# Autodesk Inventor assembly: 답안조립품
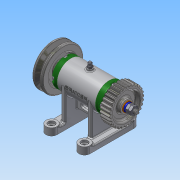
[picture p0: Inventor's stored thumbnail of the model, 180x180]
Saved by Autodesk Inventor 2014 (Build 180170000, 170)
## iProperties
Created: 2015-11
Part Number: 답안조립품
Document SubType Name: Assembly
Designer: 103-18
Author: 103-18
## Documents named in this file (16)
- C:\Users\103-18\Desktop\451110V1026\답안조립품.iam
- C:\Users\103-18\Desktop\451110V1026\1-본체.ipt
- C:\Users\103-18\Desktop\451110V1026\베어링 15 x 32 x 9.ipt
- C:\Users\103-18\Desktop\451110V1026\오일 실 15 25 7.ipt
- C:\Users\103-18\Desktop\451110V1026\커버.ipt
- C:\Users\103-18\Desktop\451110V1026\볼트 M4 x 12.ipt
- C:\Users\103-18\Desktop\451110V1026\축.ipt
- C:\Users\103-18\Desktop\451110V1026\키 3 x 3 x 12.ipt
- C:\Users\103-18\Desktop\451110V1026\V벨트풀리.ipt
- C:\Users\103-18\Desktop\451110V1026\스퍼기어.ipt
- C:\Users\103-18\Desktop\451110V1026\너트 M 8.ipt
- C:\Users\103-18\Desktop\451110V1026\스프링와셔 8.ipt
- C:\Users\103-18\Desktop\451110V1026\와셔 8x17.ipt
- C:\Users\103-18\Desktop\451110V1026\니플 M 6 x 0.75.ipt
- C:\Users\103-18\Desktop\451110V1026\볼트 M 6 x 8.ipt
- C:\Users\103-18\Desktop\451110V1026\와셔 6x11.5.ipt
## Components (12 placed, 4 different names)
1. 1-본체:1
2. KS B 2023 6002 - 15 x 32 x 9:1
3. KS B 2023 6002 - 15 x 32 x 9:2
4. V벨트풀리:1 — 각도:4
5. ISO 4762 M4 x 12:1
6. ISO 4762 M4 x 12:3
7. ISO 4762 M4 x 12:4
8. ISO 4762 M4 x 12:5
9. ISO 4762 M4 x 12:2
10. ISO 4762 M4 x 12:6
11. ISO 4762 M4 x 12:7
12. ISO 4762 M4 x 12:8
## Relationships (1: Angle 1)
- 각도:4 [Angle]: V벨트풀리:1
